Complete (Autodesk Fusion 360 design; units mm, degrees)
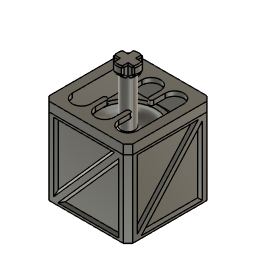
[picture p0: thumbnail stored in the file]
sketch "Sketch1" plane through (0, 0, 0) normal (0, 1, 0) x axis (1, 0, 0)
  line L1 (0, -1.0393) -> (0, 0)
  line L2 (0, -6.5393) -> (0, -1.0393)
  line L3 (7, -13.5223) -> (6, -13.5223)
  line L4 (7, -16.5) -> (7, -13.5223)
  line L5 (9, -16.5) -> (7, -16.5)
  line L6 (9, 0) -> (9, -16.5)
  line L7 (0, 0) -> (9, 0)
  line L8 (1.5, -23.3515) -> (1.5, -13.3515)
  line L9 (3, -2.5393) -> (0, -2.5393)
  line L10 (2.4121, -24.2636) -> (1.5, -23.3515)
  line L11 (2.4121, -27) -> (2.4121, -24.2636)
  line L12 (0, -27) -> (2.4121, -27)
  line L13 (0, 0) -> (0, -27)
  arc A1 centre (0, -6.5393) radius 5.5 clockwise from (0, -1.0393) to (4.4732, -9.7394)
  arc A2 centre (6.6757, -11.05) radius 2.5629 clockwise from (6, -13.5223) to (4.4732, -9.7394)
  arc A3 centre (4.8794, -13.3515) radius 3.3794 clockwise from (1.5, -13.3515) to (2.9115, -10.6041)
  arc A4 centre (0, -6.5393) radius 5 clockwise from (3, -2.5393) to (2.9115, -10.6041)
  point P1 (0, 0)
  point P2 (0, 0)
  point P4 (0, -6.5393)
  point P5 (0, -6.5393)
  point P13 (0, 0)
  point P18 (0, -2.5393)
  point P24 (0, 0)
  point P3 (0, -1.0393)
  point P19 (3, -2.5393)
  point P15 (1.5, -13.3515)
  point P17 (1.5, -23.3515)
  point P8 (6, -13.5223)
  point P9 (7, -13.5223)
  coincident P1 P2
  vertical L1
  parallel L1 L2
  coincident P4 P5
  horizontal L3
  perpendicular L3 L4
  perpendicular L4 L5
  perpendicular L5 L6
  coincident P1 P13
  perpendicular L1 L7
  tangent A3 L8
  coincident L2 P18
  parallel L8 L11
  perpendicular L11 L12
  coincident P1 P24
  perpendicular L7 L13
  tangent A3 A4
  dimension "d1" distance P3 P4 = 5.5
  dimension "d4" distance P18 P19 = 3
  dimension "d5" distance P15 P17 = 10
  dimension "d6" distance L8 L13 = 1.5
  dimension "d13" distance P8 P9 = 1
revolve "Revolve1" sketch "Sketch1" AlongAngle 360
revolve "Revolve1" sketch "Sketch1" AlongAngle 360
sketch "Sketch4" plane through (0, 0, 16.5) normal (0, 0, 1) x axis (-1, 0, 0)
  line L1 (-9, -9) -> (9, -9)
  line L2 (-9, 9) -> (-9, -9)
  line L3 (9, 9) -> (-9, 9)
  line L4 (9, -9) -> (9, 9)
  line L5 (-7, -7) -> (7, -7)
  line L6 (-7, 7) -> (-7, -7)
  line L7 (7, 7) -> (-7, 7)
  line L8 (7, -7) -> (7, 7)
  circle C1 centre (0, 0) radius 9
  circle C2 centre (0, 0) radius 7
  circle C3 centre (0, 0) radius 9
  horizontal L1
  vertical L2
  horizontal L3
  vertical L4
  horizontal L5
  vertical L6
  horizontal L7
  vertical L8
  concentric C1 C3
  tangent L1 C3
extrude "Extrude4" add sketch "Sketch4" profile of C1 L1 L2 L3 L4 L5 L6 L7 L8 C3 against normal blind 16.5
extrude "Extrude5" cut sketch "Sketch4" profile of C1 C2 L5 L6 L7 L8 C3 against normal blind 3
sketch "Sketch5" plane through (0, -9, 0) normal (0, -1, 0) x axis (1, 0, 0)
  line L1 (-9, 16.5) -> (9, 16.5)
  line L2 (-9, 0) -> (-9, 16.5)
  line L3 (9, 0) -> (-9, 0)
  line L4 (9, 16.5) -> (9, 0)
  line L5 (6.5, 1) -> (-6.5, 1)
  line L6 (6.5, 15.5) -> (6.5, 1)
  line L7 (-6.5, 15.5) -> (6.5, 15.5)
  line L8 (-6.5, 1) -> (-6.5, 15.5)
  line L9 (6.5, 14) -> (-5, 1)
  line L10 (-6.5, 2.5) -> (5, 15.5)
  point P10 (-6.5, 2.5)
  point P11 (-5, 1)
  point P12 (6.5, 14)
  point P13 (5, 15.5)
  horizontal L5
  vertical L6
  horizontal L7
  vertical L8
  coincident L8 P10
  coincident L5 P11
  coincident L6 P12
  coincident L7 P13
extrude "Extrude6" cut sketch "Sketch5" profile of L5 L6 L7 L8 L9 L10 against normal blind 0.5
sketch "Sketch6" plane through (9, 0, 0) normal (1, 0, 0) x axis (0, 1, 0)
  line L1 (-9, 16.5) -> (9, 16.5)
  line L2 (-9, 0) -> (-9, 16.5)
  line L3 (9, 0) -> (-9, 0)
  line L4 (9, 16.5) -> (9, 0)
  line L5 (6.5, 1) -> (-6.5, 1)
  line L6 (-6.5, 15.5) -> (6.5, 15.5)
  line L7 (-6.5, 1) -> (-6.5, 15.5)
  line L8 (6.5, 15.5) -> (6.5, 1)
  line L9 (6.5, 14) -> (-5, 1)
  line L10 (-6.5, 2.5) -> (5, 15.5)
  point P8 (-6.5, 2.5)
  point P9 (-5, 1)
  point P13 (6.5, 14)
  point P7 (5, 15.5)
  horizontal L5
  vertical L8
  horizontal L6
  vertical L7
  coincident P8 L7
  coincident P9 L5
  coincident P13 L8
  coincident P7 L6
sketch "Sketch7" plane through (0, 9, 0) normal (0, 1, 0) x axis (-1, 0, 0)
  line L1 (-9, 16.5) -> (9, 16.5)
  line L2 (-9, 0) -> (-9, 16.5)
  line L3 (9, 0) -> (-9, 0)
  line L4 (9, 16.5) -> (9, 0)
  line L5 (6.5, 1) -> (-6.5, 1)
  line L6 (-6.5, 15.5) -> (6.5, 15.5)
  line L7 (-6.5, 1) -> (-6.5, 15.5)
  line L8 (6.5, 15.5) -> (6.5, 1)
  line L9 (6.5, 14) -> (-5, 1)
  line L10 (-6.5, 2.5) -> (5, 15.5)
  point P8 (-6.5, 2.5)
  point P9 (-5, 1)
  point P13 (6.5, 14)
  point P7 (5, 15.5)
  horizontal L5
  vertical L8
  horizontal L6
  vertical L7
  coincident P8 L7
  coincident P9 L5
  coincident P13 L8
  coincident P7 L6
sketch "Sketch8" plane through (-9, 0, 0) normal (-1, 0, 0) x axis (0, -1, 0)
  line L1 (-9, 16.5) -> (9, 16.5)
  line L2 (-9, 0) -> (-9, 16.5)
  line L3 (9, 0) -> (-9, 0)
  line L4 (9, 16.5) -> (9, 0)
  line L5 (6.5, 1) -> (-6.5, 1)
  line L6 (-6.5, 15.5) -> (6.5, 15.5)
  line L7 (-6.5, 1) -> (-6.5, 15.5)
  line L8 (6.5, 15.5) -> (6.5, 1)
  line L9 (6.5, 14) -> (-5, 1)
  line L10 (-6.5, 2.5) -> (5, 15.5)
  point P8 (-6.5, 2.5)
  point P9 (-5, 1)
  point P13 (6.5, 14)
  point P7 (5, 15.5)
  horizontal L5
  vertical L8
  horizontal L6
  vertical L7
  coincident P8 L7
  coincident P9 L5
  coincident P13 L8
  coincident P7 L6
extrude "Extrude7" cut sketch "Sketch8" profile of L5 L6 L7 L8 L9 L10 against normal blind 0.5
extrude "Extrude8" cut sketch "Sketch7" profile of L5 L6 L7 L8 L9 L10 against normal blind 0.5
extrude "Extrude9" cut sketch "Sketch6" profile of L5 L6 L7 L8 L9 L10 against normal blind 0.5
chamfer "Chamfer1" distance 0.5
chamfer "Chamfer2" distance 1
joint "Assemble1" alignAngle 0 alignOffsetX 0 alignOffsetY 0 alignOffsetZ 0
sketch "Sketch9" plane through (0, 0, 16.5) normal (0, 0, 1) x axis (-1, 0, 0)
  line L1 (7, -7) -> (7, 7)
  line L2 (-7, -7) -> (7, -7)
  line L3 (-7, 7) -> (-7, -7)
  line L4 (7, 7) -> (-7, 7)
  line L5 (-9, 8) -> (-8, 9)
  line L6 (-9, -8) -> (-9, 8)
  line L7 (-8, -9) -> (-9, -8)
  line L8 (8, -9) -> (-8, -9)
  line L9 (9, -8) -> (8, -9)
  line L10 (9, 8) -> (9, -8)
  line L11 (8, 9) -> (9, 8)
  line L12 (-8, 9) -> (8, 9)
  line L13 (-7, -7) -> (7, -7)
  line L14 (-7, 7) -> (-7, -7)
  line L15 (7, 7) -> (-7, 7)
  line L16 (7, -7) -> (7, 7)
  line L17 (9, -8) -> (8, -9)
  line L18 (9, 8) -> (9, -8)
  line L19 (9, 8) -> (8, 9)
  line L20 (-8, 9) -> (8, 9)
  line L21 (-9, 8) -> (-8, 9)
  line L22 (-9, -8) -> (-9, 8)
  line L23 (-8, -9) -> (-9, -8)
  line L24 (8, -9) -> (-8, -9)
  line L25 (7, 5) -> (7, -5)
  line L26 (3, -5) -> (3, 5)
  line L27 (5, 5) -> (5, -5)
  line L28 (-3, 5) -> (-3, -5)
  line L29 (-7, -5) -> (-7, 5)
  line L30 (-5, 5) -> (-5, -5)
  line L31 (2, 5) -> (2, -5)
  line L32 (-2, -5) -> (-2, 5)
  line L33 (0, 5) -> (0, -5)
  line L34 (-5, 2) -> (5, 2)
  line L35 (5, -2) -> (-5, -2)
  line L36 (-5, 0) -> (5, 0)
  line L37 (-7.9, -7.9) -> (7.9, -7.9)
  line L38 (-7.9, 7.9) -> (-7.9, -7.9)
  line L39 (7.9, 7.9) -> (-7.9, 7.9)
  line L40 (7.9, -7.9) -> (7.9, 7.9)
  arc A1 centre (5, 5) radius 2 clockwise from (3, 5) to (7, 5)
  arc A2 centre (5, -5) radius 2 clockwise from (7, -5) to (3, -5)
  arc A3 centre (-5, 5) radius 2 clockwise from (-7, 5) to (-3, 5)
  arc A4 centre (-5, -5) radius 2 clockwise from (-3, -5) to (-7, -5)
  arc A5 centre (0, 5) radius 2 clockwise from (-2, 5) to (2, 5)
  arc A6 centre (0, -5) radius 2 clockwise from (2, -5) to (-2, -5)
  arc A7 centre (-5, 0) radius 2 clockwise from (-5, -2) to (-5, 2)
  arc A8 centre (5, 0) radius 2 clockwise from (5, 2) to (5, -2)
  point P5 (-7, 7)
  point P16 (-7, 7)
  point P3 (7, -7)
  point P14 (7, -7)
  point P10 (8, -9)
  point P18 (8, -9)
  point P11 (9, -8)
  point P19 (9, -8)
  point P12 (9, 8)
  point P20 (9, 8)
  point P13 (8, 9)
  point P21 (8, 9)
  point P6 (-8, 9)
  point P22 (-8, 9)
  point P7 (-9, 8)
  point P23 (-9, 8)
  point P8 (-9, -8)
  point P24 (-9, -8)
  point P25 (-9, -8)
  point P9 (-8, -9)
  point P26 (-8, -9)
  point P50 (-5, 0)
  point P1 (0, 0)
  point P51 (0, 0)
  horizontal L13
  vertical L14
  horizontal L15
  vertical L16
  coincident P5 P16
  coincident P3 P14
  coincident P10 P18
  coincident P11 P19
  coincident P12 P20
  coincident P13 P21
  coincident P6 P22
  coincident P7 P23
  coincident P8 P24
  coincident P8 P25
  coincident P9 P26
  tangent L25 A1
  tangent A1 L26
  parallel L25 L26
  tangent L26 A2
  tangent L25 A2
  perpendicular L13 L27
  tangent L28 A3
  tangent A3 L29
  parallel L28 L29
  tangent L29 A4
  tangent L28 A4
  perpendicular L13 L30
  tangent L31 A5
  tangent A5 L32
  parallel L31 L32
  tangent L32 A6
  tangent L31 A6
  parallel L28 L33
  tangent L34 A7
  tangent A7 L35
  parallel L34 L35
  tangent L35 A8
  tangent L34 A8
  midpoint L30 P50
  perpendicular L30 L36
  coincident P1 P51
  midpoint L36 P51
  horizontal L37
  vertical L38
  horizontal L39
  vertical L40
  dimension "d54" distance L15 L39 = 0.9
  dimension "d55" distance L29 L38 = 0.9
  dimension "d56" distance L16 L40 = 0.9
  dimension "d57" distance L13 L37 = 0.9
extrude "Extrude1" new body sketch "Sketch9" profile of L1 L2 L3 L4 L5 L6 L7 L8 L9 L10 L11 L12 L13 L14 L15 L16 L17 L18 L19 L20 L21 L22 L23 L24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 along normal blind 2
extrude "Extrude10" cut sketch "Sketch9" profile of L1 L2 L3 L4 L13 L14 L15 L16 L25 L29 L37 L38 L39 L40 against normal blind 3
sketch "Sketch10" plane through (0, 0, 16.5) normal (0, 0, -1) x axis (1, 0, 0)
  line L1 (3, -2) -> (3, -5)
  line L2 (2, -2) -> (3, -2)
  line L3 (2, -5) -> (2, -2)
  line L4 (-2, -2) -> (-2, -5)
  line L5 (-3, -2) -> (-2, -2)
  line L6 (-3, -5) -> (-3, -2)
  line L7 (-7, 5) -> (-7, -5)
  line L8 (-3, 2) -> (-3, 5)
  line L9 (-2, 2) -> (-3, 2)
  line L10 (-2, 5) -> (-2, 2)
  line L11 (2, 2) -> (2, 5)
  line L12 (3, 2) -> (2, 2)
  line L13 (3, 5) -> (3, 2)
  line L14 (7, -5) -> (7, 5)
  line L15 (-8, 9) -> (8, 9)
  line L16 (-9, 8) -> (-8, 9)
  line L17 (-9, -8) -> (-9, 8)
  line L18 (-8, -9) -> (-9, -8)
  line L19 (8, -9) -> (-8, -9)
  line L20 (9, -8) -> (8, -9)
  line L21 (9, 8) -> (9, -8)
  line L22 (8, 9) -> (9, 8)
  line L23 (-3, 7) -> (-3, 2.5)
  line L24 (-7, 7) -> (-3, 7)
  line L25 (-7, -7) -> (-7, 7)
  line L26 (-3, -7) -> (-7, -7)
  line L27 (-3, -2.5) -> (-3, -7)
  line L28 (-2, -7) -> (-2, -2.5)
  line L29 (2, -7) -> (-2, -7)
  line L30 (2, -2.5) -> (2, -7)
  line L31 (3, -7) -> (3, -2.5)
  line L32 (7, -7) -> (3, -7)
  line L33 (7, 7) -> (7, -7)
  line L34 (3, 7) -> (7, 7)
  line L35 (3, 2.5) -> (3, 7)
  line L36 (2, 7) -> (2, 2.5)
  line L37 (-2, 7) -> (2, 7)
  line L38 (-2, 2.5) -> (-2, 7)
  line L39 (-3, 7) -> (-3, 2.5)
  line L40 (2, 7) -> (3, 7)
  line L41 (-3, 7) -> (-2, 7)
  line L42 (-2, -7) -> (-3, -7)
  line L43 (-2, -2.5) -> (-3, -2.5)
  line L44 (3, -7) -> (2, -7)
  line L45 (3, -2.5) -> (2, -2.5)
  line L46 (2, -2) -> (2, -2.5)
  line L47 (3, -2.5) -> (3, -2)
  line L48 (2, -2) -> (3, -2)
  line L49 (-2, -2) -> (-2, -2.5)
  line L50 (-3, -2) -> (-2, -2)
  line L51 (-3, -2.5) -> (-3, -2)
  line L52 (-3, 2) -> (-3, 2.5)
  line L53 (-2, 2) -> (-3, 2)
  line L54 (-2, 2) -> (-2, 2.5)
  line L55 (2, 2) -> (2, 2.5)
  line L56 (2, 2) -> (3, 2)
  line L57 (3, 2.5) -> (3, 2)
  line L58 (-2, 2.5) -> (-3, 2.5)
  line L59 (3, 2.5) -> (2, 2.5)
  arc A1 centre (0, -5) radius 2 clockwise from (2, -5) to (-2, -5)
  arc A2 centre (-5, -5) radius 2 clockwise from (-3, -5) to (-7, -5)
  arc A3 centre (-5, 5) radius 2 clockwise from (-7, 5) to (-3, 5)
  arc A4 centre (0, 5) radius 2 clockwise from (-2, 5) to (2, 5)
  arc A5 centre (5, 5) radius 2 clockwise from (3, 5) to (7, 5)
  arc A6 centre (5, -5) radius 2 clockwise from (7, -5) to (3, -5)
  arc A7 centre (-2.5, -2.5) radius 0.5 clockwise from (-3, -2.5) to (-2, -2.5)
  arc A8 centre (2.5, -2.5) radius 0.5 clockwise from (2, -2.5) to (3, -2.5)
  arc A9 centre (2.5, 2.5) radius 0.5 clockwise from (3, 2.5) to (2, 2.5)
  arc A10 centre (-2.5, 2.5) radius 0.5 clockwise from (-2, 2.5) to (-3, 2.5)
  point P38 (-3, -2.5)
  point P37 (-2, -2.5)
  point P41 (2, -2.5)
  point P40 (3, -2.5)
  point P43 (2, 2.5)
  point P44 (3, 2.5)
  point P46 (-3, 2.5)
  point P47 (-2, 2.5)
  point P4 (2, -2)
  point P60 (2, -2)
  point P3 (3, -2)
  point P61 (3, -2)
  point P62 (3, -2)
  point P63 (2, -2)
  point P8 (-2, -2)
  point P64 (-2, -2)
  point P9 (-3, -2)
  point P65 (-3, -2)
  point P16 (-3, 2)
  point P66 (-3, 2)
  point P17 (-2, 2)
  point P67 (-2, 2)
  point P21 (2, 2)
  point P68 (2, 2)
  point P22 (3, 2)
  point P69 (3, 2)
  coincident L6 P38
  coincident L4 P37
  coincident L3 P41
  coincident L1 P40
  coincident L11 P43
  coincident L13 P44
  coincident L8 P46
  coincident L10 P47
  tangent A10 L23
  parallel L8 L23
  perpendicular L8 L24
  perpendicular L24 L25
  perpendicular L7 L26
  tangent A7 L27
  tangent A7 L28
  parallel L4 L28
  perpendicular L28 L29
  tangent A8 L30
  tangent A8 L31
  parallel L1 L31
  perpendicular L31 L32
  perpendicular L32 L33
  perpendicular L14 L34
  tangent A9 L35
  tangent A9 L36
  parallel L11 L36
  perpendicular L23 L37
  tangent A10 L38
  perpendicular L36 L40
  perpendicular L23 L41
  perpendicular L28 L42
  perpendicular L28 L43
  perpendicular L31 L44
  perpendicular L1 L45
  coincident P4 P60
  coincident P3 P61
  coincident P3 P62
  coincident P4 P63
  coincident P8 P64
  coincident P9 P65
  coincident P16 P66
  tangent A10 L52
  coincident P17 P67
  tangent A10 L54
  coincident P21 P68
  coincident P22 P69
  tangent A9 L57
extrude "Extrude2" cut sketch "Sketch10" profile of L1 L2 L3 L4 L5 L6 L8 L9 L10 L11 L12 L13 A7 A8 A9 A10 L46 L47 L48 L49 L50 L51 L52 L53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 against normal blind 4
extrude "Extrude3" cut sketch "Sketch10" profile of L1 L3 A1 L4 L6 A2 A3 L8 L10 A4 L11 L13 A5 A6 A7 A8 A9 A10 L23 L24 L25 L26 L27 L28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 against normal blind 1
sketch "Sketch11" plane through (0, 0, 27) normal (0, 0, 1) x axis (-1, 0, 0)
  line L1 (-1.0607, 1.0607) -> (1.0607, 1.0607)
  line L2 (1.0607, -1.0607) -> (1.0607, 1.0607)
  line L3 (-1.0607, -1.0607) -> (1.0607, -1.0607)
  line L4 (-1.0607, 1.0607) -> (-1.0607, -1.0607)
  line L5 (1.0607, 2.1664) -> (1.0607, 1.0607)
  line L6 (-1.0607, 2.4) -> (-1.0607, 1.0607)
  line L7 (1.0607, 2.4) -> (-1.0607, 2.4)
  line L8 (1.0607, 2.1664) -> (1.0607, 2.4)
  line L9 (2.6, 1.0607) -> (1.0607, 1.0607)
  line L10 (2.6, -1.0607) -> (2.6, 1.0607)
  line L11 (1.0607, -1.0607) -> (2.6, -1.0607)
  line L12 (1.0607, -2.5) -> (1.0607, -1.0607)
  line L13 (-1.0607, -2.5) -> (1.0607, -2.5)
  line L14 (-1.0607, -1.0607) -> (-1.0607, -2.5)
  line L15 (-2.9, -1.0607) -> (-1.0607, -1.0607)
  line L16 (-2.9, 1.0607) -> (-2.9, -1.0607)
  line L17 (-1.0607, 1.0607) -> (-2.9, 1.0607)
  line L18 (2.6, 2.4) -> (-2.9, 2.4)
  line L19 (2.6, -2.5) -> (2.6, 2.4)
  line L20 (-2.9, -2.5) -> (2.6, -2.5)
  line L21 (-2.9, 2.4) -> (-2.9, -2.5)
  circle C1 centre (0, 0) radius 2.4121
  circle C2 centre (0, 0) radius 1.5
  point P1 (0, 0)
  point P3 (0, 0)
  point P4 (1.0607, 1.0607)
  point P5 (-1.0607, 1.0607)
  point P6 (1.0607, -1.0607)
  point P7 (-1.0607, -1.0607)
  point P8 (1.0607, 2.1664)
  coincident P1 P3
  coincident C2 P4
  coincident C2 P5
  horizontal L1
  coincident C2 P6
  perpendicular L1 L2
  equal L1 L2
  coincident C2 P7
  perpendicular L2 L3
  coincident C1 P8
  perpendicular L1 L5
  perpendicular L1 L6
  perpendicular L4 L7
  perpendicular L1 L8
  perpendicular L5 L9
  perpendicular L3 L10
  perpendicular L2 L11
  perpendicular L9 L12
  perpendicular L4 L13
  perpendicular L3 L14
  perpendicular L14 L15
  perpendicular L1 L16
  perpendicular L4 L17
  horizontal L18
  vertical L19
  horizontal L20
  vertical L21
  dimension "d41" diameter C2 = 3
extrude "Extrude1" cut sketch "Sketch11" profile of C1 L5 L6 L9 L11 L12 L14 L15 L17 against normal blind 5.5
extrude "Extrude2" cut of existing geometry blind -1
chamfer "Chamfer1" distance 0.25
extrude "Extrude4" add sketch "Sketch9" profile of L1 L2 L3 L4 L13 L14 L15 L16 L25 L29 L37 L38 L39 L40 against normal blind 2.9
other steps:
create_component "CreateComponent1"
create_component "CreateComponent2"
joint_origin "JointOrigin2"
joint_origin "JointOrigin2"
create_component "CreateComponent3"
